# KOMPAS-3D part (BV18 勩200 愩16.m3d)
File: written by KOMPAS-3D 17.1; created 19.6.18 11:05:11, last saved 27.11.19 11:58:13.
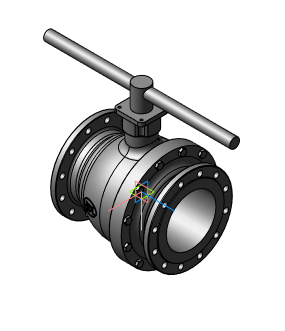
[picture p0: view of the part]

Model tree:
1. Операция без истории:2  (labels: Сталь 20  ГОСТ 1050-2013)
